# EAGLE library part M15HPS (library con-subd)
SUB-D
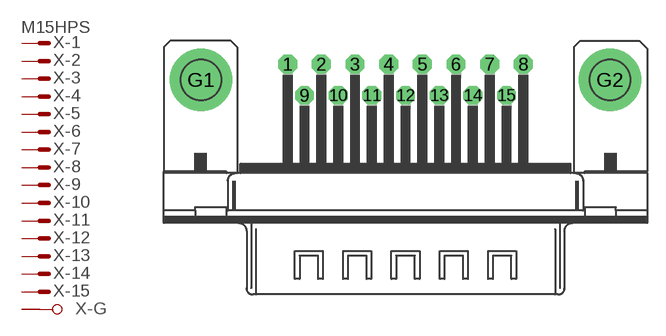
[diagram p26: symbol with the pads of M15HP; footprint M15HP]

Designator prefix X; gates -2=M -3=M -4=M -5=M -6=M -7=M -8=M -9=M -10=M -11=M -12=M -13=M -14=M -15=M -G=GND -1=MV

## M15HPS (OC_FARNELL: unknown; OC_NEWARK: unknown)  [M15HP]
1  -1:M  pas
2  -2:M  pas
3  -3:M  pas
4  -4:M  pas
5  -5:M  pas
6  -6:M  pas
7  -7:M  pas
8  -8:M  pas
9  -9:M  pas
10  -10:M  pas
11  -11:M  pas
12  -12:M  pas
13  -13:M  pas
14  -14:M  pas
15  -15:M  pas
G1  -G:G1  pas
G2  -G:G2  pas

## Footprint M15HP (pad centres in mm)
SUB-D
drill 1.016 octagon: 1 -9.601,1.27; 2 -6.858,1.27; 3 -4.115,1.27; 4 -1.372,1.27; 5 1.372,1.27; 6 4.115,1.27; 7 6.858,1.27; 8 9.601,1.27; 9 -8.23,-1.27; 10 -5.486,-1.27; 11 -2.743,-1.27; 12 0,-1.27; 13 2.743,-1.27; 14 5.486,-1.27; 15 8.23,-1.27
drill 3.302 pad 5.08 round: G1 -16.662,0; G2 16.662,0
